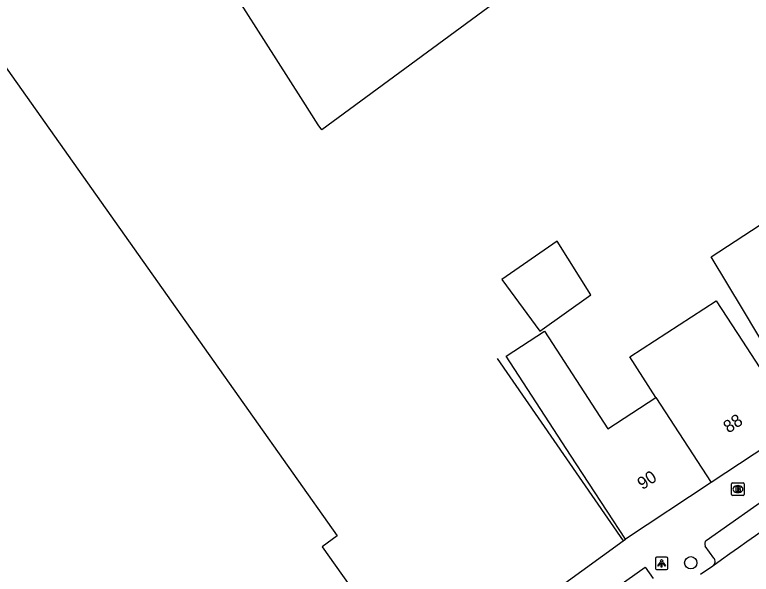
# Model space of a CAD drawing. Extents: x 159718 to 160783, y 383290 to 384030.
# Drawn here: x 160388.6 to 160447.6, y 383359.4 to 383404.2 of the extents above; entities that cross this region are included whole.
import ezdxf

# ---------------------------------------------------------------- set-up
doc = ezdxf.new("R2010")
doc.units = 0
for name, color, linetype in [('IMGEO_Boom', 7, 'Continuous'), ('IMGEO_Brandkraan', 7, 'Continuous'), ('IMGEO_Hek', 7, 'Continuous'), ('IMGEO_Lichtpunt', 7, 'Continuous'), ('IMGEO_Pand', 7, 'Continuous'), ('IMGEO_Pand_nummerreeks', 7, 'Continuous'), ('IMGEO_Rijbaan_lokaal_open', 7, 'Continuous'), ('IMGEO_Voetpad_open', 7, 'Continuous')]:
    doc.layers.add(name, color=color, linetype=linetype)

msp = doc.modelspace()

# ---------------------------------------------------------------- linework, layer by layer
at = {"layer": 'IMGEO_Boom'}
msp.add_circle((160442.722, 383360.283), 0.489, dxfattribs=at)
at = {"layer": 'IMGEO_Brandkraan'}
for p, q in [((160445.993, 383365.758), (160445.993, 383366.61)), ((160446.068, 383366.684), (160446.92, 383366.684)), ((160446.481, 383366.464), (160446.506, 383366.464)), ((160446.994, 383366.61), (160446.994, 383365.758)), ((160446.92, 383365.684), (160446.068, 383365.684)), ((160446.504, 383365.904), (160446.479, 383365.904))]:
    msp.add_line(p, q, dxfattribs=at)
for points in [[(160445.993, 383365.758), (160445.993, 383366.61)], [(160446.068, 383366.684), (160446.92, 383366.684)], [(160446.341, 383366.384), (160446.341, 383365.984), (160446.554, 383365.984)], [(160446.572, 383366.384), (160446.341, 383366.384)], [(160446.52, 383366.303), (160446.466, 383366.303), (160446.466, 383366.227)], [(160446.466, 383366.227), (160446.519, 383366.227)], [(160446.994, 383366.61), (160446.994, 383365.758)], [(160446.92, 383365.684), (160446.068, 383365.684)], [(160446.528, 383366.151), (160446.466, 383366.151), (160446.466, 383366.07)], [(160446.466, 383366.07), (160446.528, 383366.07)]]:
    msp.add_lwpolyline(points, dxfattribs=at)
for centre, radius, start, end in [((160446.07, 383366.608), 0.0765, 91.55205, 178.44795), ((160446.07, 383366.608), 0.0765, 91.55205, 178.44795), ((160446.521, 383366.265), 0.0379, 267.82845, 90.93552), ((160446.576, 383366.239), 0.145, 59.4692, 91.53667), ((160446.601, 383366.286), 0.0922, 285.51372, 58.15012), ((160446.606, 383366.094), 0.105, 301.31148, 78.98903), ((160446.918, 383366.608), 0.0765, 1.55205, 88.44795), ((160446.918, 383366.608), 0.0765, 1.55205, 88.44795), ((160446.07, 383365.76), 0.0765, 181.55205, 268.44795), ((160446.07, 383365.76), 0.0765, 181.55205, 268.44795), ((160446.529, 383366.11), 0.0404, 269.87594, 90.50774), ((160446.56, 383366.235), 0.251, 268.66757, 293.53466), ((160446.918, 383365.76), 0.0765, 271.55205, 358.44795), ((160446.918, 383365.76), 0.0765, 271.55205, 358.44795)]:
    msp.add_arc(centre, radius, start, end, dxfattribs=at)
for centre, major_axis, ratio, start_param, end_param in [((160446.48, 383366.184), (-0.387, 0.002), 0.722429, 4.712389, 7.853982), ((160446.505, 383366.184), (-0.39, 0.002), 0.717154, 1.570796, 4.712389)]:
    msp.add_ellipse(centre, major_axis=major_axis, ratio=ratio, start_param=start_param, end_param=end_param, dxfattribs=at)
at = {"layer": 'IMGEO_Hek'}
msp.add_lwpolyline([(160427.225, 383376.647), (160437.31, 383362.051)], dxfattribs=at)
at = {"layer": 'IMGEO_Lichtpunt'}
for p, q in [((160439.887, 383360.635), (160439.887, 383359.828)), ((160439.887, 383360.635), (160439.887, 383359.828)), ((160440.789, 383360.73), (160439.981, 383360.73)), ((160440.789, 383360.73), (160439.981, 383360.73)), ((160440.883, 383359.828), (160440.883, 383360.635)), ((160440.883, 383359.828), (160440.883, 383360.635)), ((160439.981, 383359.734), (160440.789, 383359.734)), ((160439.981, 383359.734), (160440.789, 383359.734))]:
    msp.add_line(p, q, dxfattribs=at)
for points in [[(160440.261, 383360.299), (160440.3, 383360.271), (160440.112, 383360.009), (160440.074, 383360.036), (160440.261, 383360.299)], [(160440.473, 383360.271), (160440.511, 383360.298), (160440.698, 383360.036), (160440.659, 383360.008), (160440.473, 383360.271)], [(160440.363, 383360.251), (160440.41, 383360.251), (160440.41, 383359.929), (160440.363, 383359.929), (160440.363, 383360.251)]]:
    msp.add_lwpolyline(points, dxfattribs=at)
msp.add_circle((160440.386, 383360.433), 0.0994, dxfattribs=at)
for centre, start, end in [((160439.981, 383360.635), 90, 180), ((160439.981, 383360.635), 90, 180), ((160440.789, 383360.635), 0, 90), ((160440.789, 383360.635), 0, 90), ((160439.981, 383359.828), 180, 270), ((160439.981, 383359.828), 180, 270), ((160440.789, 383359.828), 270, 0), ((160440.789, 383359.828), 270, 360)]:
    msp.add_arc(centre, 0.0946, start, end, dxfattribs=at)
at = {"layer": 'IMGEO_Pand'}
for points in [[(160442.432, 383416.62), (160430.456, 383407.79), (160430.494, 383407.738), (160413.176, 383394.97), (160412.886, 383395.363), (160411.667, 383397.277), (160409.521, 383400.648), (160401.872, 383412.66), (160400.732, 383411.937), (160388.97, 383428.187)], [(160385.354, 383403.497), (160403.744, 383377.513), (160414.411, 383362.435), (160413.196, 383361.572), (160415.866, 383357.791), (160418.223, 383354.454), (160420.196, 383351.659)], [(160452.206, 383371.794), (160449.618, 383376.073), (160448.023, 383378.711), (160446.952, 383380.482), (160444.345, 383384.793), (160448.905, 383387.761), (160450.33, 383385.571)], [(160427.584, 383382.987), (160430.624, 383378.837), (160434.711, 383381.762), (160432.011, 383386.047), (160427.584, 383382.987)], [(160439.935, 383373.529), (160437.834, 383376.773), (160444.746, 383381.265), (160446.855, 383378.026), (160448.538, 383375.441), (160451.256, 383371.244)], [(160437.485, 383362.177), (160433.087, 383368.905), (160427.932, 383376.842), (160431.019, 383378.841), (160436.081, 383371.024), (160439.935, 383373.529)], [(160439.935, 383373.529), (160444.357, 383366.701)], [(160451.256, 383371.244), (160444.357, 383366.701)], [(160444.357, 383366.701), (160437.485, 383362.177)]]:
    msp.add_lwpolyline(points, dxfattribs=at)
at = {"layer": 'IMGEO_Rijbaan_lokaal_open'}
msp.add_lwpolyline([(160443.496, 383359.361), (160444.501, 383360.024)], dxfattribs=at)
msp.add_arc((160570.774, 383186.65), 214.484, 122.49811, 126.06695, dxfattribs=at)
at = {"layer": 'IMGEO_Voetpad_open'}
for points in [[(160443.967, 383362.07), (160449.647, 383366.083), (160453.854, 383368.823), (160462.448, 383374.26), (160468.041, 383377.621)], [(160420.196, 383351.659), (160421.421, 383352.526), (160422.361, 383351.197), (160432.355, 383358.426), (160437.31, 383362.051), (160437.485, 383362.177)], [(160444.57, 383360.664), (160443.881, 383361.618)], [(160433.178, 383354.4), (160432.558, 383355.302), (160439.061, 383359.924), (160439.706, 383359.02)]]:
    msp.add_lwpolyline(points, dxfattribs=at)
for centre, radius, start, end in [((160444.199, 383361.792), 0.362, 129.82513, 208.62958), ((160444.222, 383360.378), 0.451, 308.26748, 39.42566)]:
    msp.add_arc(centre, radius, start, end, dxfattribs=at)

# ---------------------------------------------------------------- texts
at = {"layer": 'IMGEO_Pand_nummerreeks'}
for s, rotation, p in [('88', 33.36333, (160445.739, 383370.628)), ('90', 33.36141, (160438.854, 383366.095))]:
    msp.add_text(s, height=1, rotation=rotation, dxfattribs=at).set_placement(p)

doc.saveas('drawing.dxf')
